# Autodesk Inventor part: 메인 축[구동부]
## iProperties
Company: 한국ATC센터
Created: 2012-05
Part Number: 메인 축[구동부]
Document SubType Name: 모델링
Designer: KYOUNG IL JANG
Mass: 168.567 g
Surface Area: 72.5109 cm^2
Volume: 21.4462 cm^3
Density: 7.86 g/cm^3
Material: 강, 연강
변환 표준: STEP AP214IS
파일 이름: C:\Users\SeoGD\Desktop\?쒗뿕\硫붿씤 異?.stp
전처리기: Build: 253, Release: 2010 SP1 - Date: Wed 07/29/2009
전송 단위: 밀리미터
불확실성: 0.01
Author: KYOUNG IL JANG
